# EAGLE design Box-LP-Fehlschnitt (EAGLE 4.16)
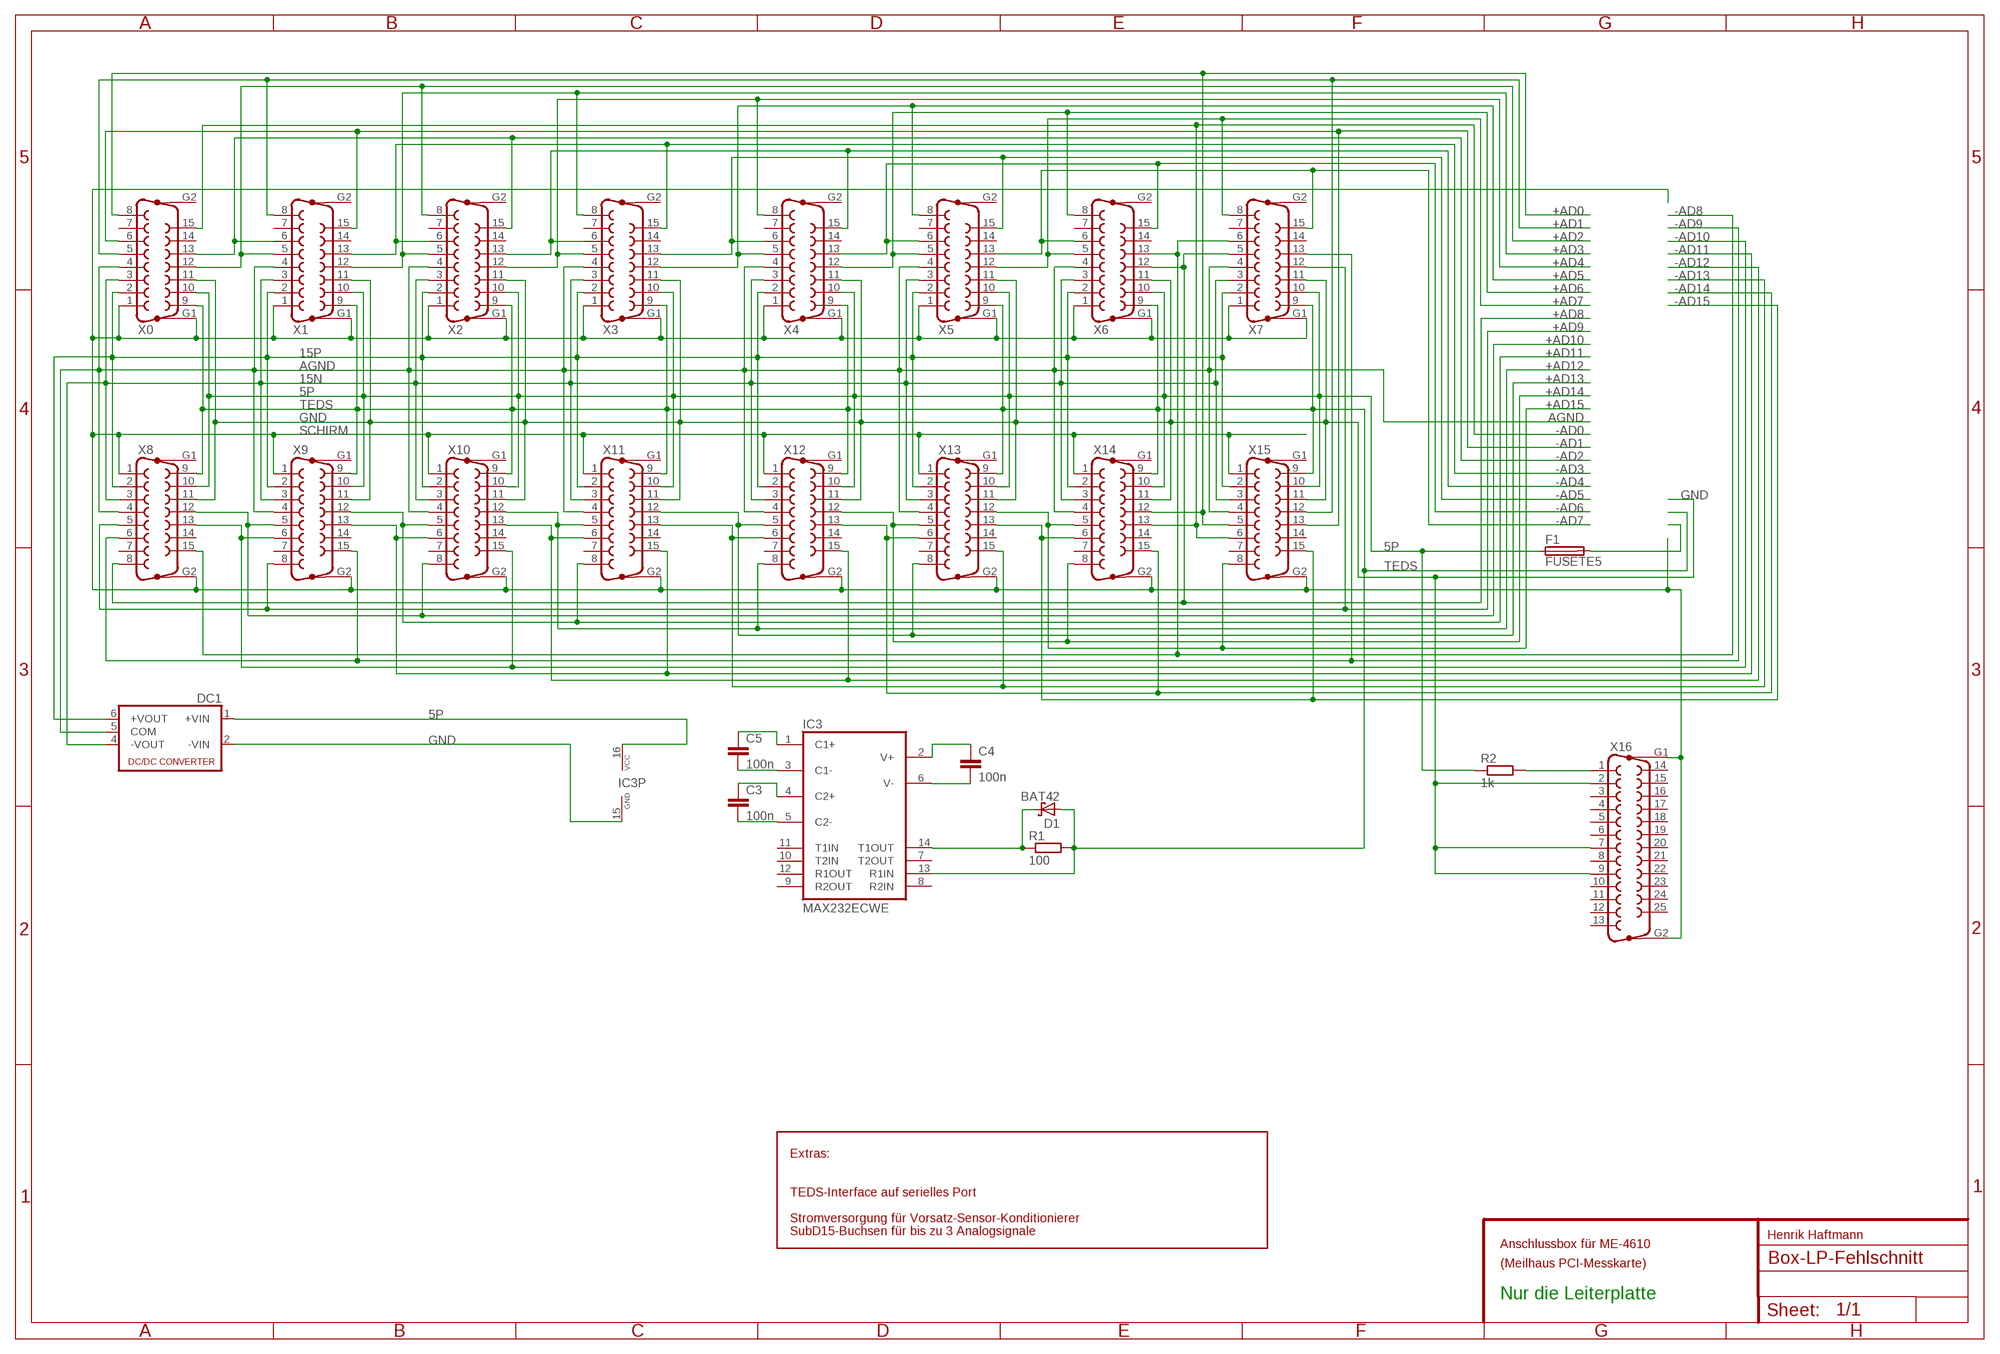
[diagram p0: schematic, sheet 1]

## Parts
C3  100n  C-EUC0603K  [C0603K]
C4  100n  C-EUC0603K  [C0603K]
C5  100n  C-EUC0603K  [C0603K]
D1  BAT42  [DO35-10]
DC1  NMA  [NMA]
F1  FUSETE5  [TE5]
IC3  MAX232ECWE  [SO16L]
R1  100  R-EU_R0805  [R0805]
R2  1k  R-EU_R0805  [R0805]
X0  F15VP  [F15VP]
X1  F15VP  [F15VP]
X2  F15VP  [F15VP]
X3  F15VP  [F15VP]
X4  F15VP  [F15VP]
X5  F15VP  [F15VP]
X6  F15VP  [F15VP]
X7  F15VP  [F15VP]
X8  F15VP  [F15VP]
X9  F15VP  [F15VP]
X10  F15VP  [F15VP]
X11  F15VP  [F15VP]
X12  F15VP  [F15VP]
X13  F15VP  [F15VP]
X14  F15VP  [F15VP]
X15  F15VP  [F15VP]
X16  F25VP  [F25VP]

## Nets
5P: DC1.1(+VIN) F1.1 IC3.16(VCC) R2.1 X0.10 X1.10 X2.10 X3.10 X4.10 X5.10 X6.10 X7.10 X8.10 X9.10 X10.10 X11.10 X12.10 X13.10 X14.10 X15.10
15N: DC1.4(-VOUT) X0.3 X1.3 X2.3 X3.3 X4.3 X5.3 X6.3 X7.3 X8.3 X9.3 X10.3 X11.3 X12.3 X13.3 X14.3 X15.3
15P: DC1.6(+VOUT) X0.2 X1.2 X2.2 X3.2 X4.2 X5.2 X6.2 X7.2 X8.2 X9.2 X10.2 X11.2 X12.2 X13.2 X14.2 X15.2
+AD0: X0.8 X14.12 X15.5
+AD1: X0.5 X1.8 X15.12
+AD2: X0.12 X1.5 X2.8
+AD3: X1.12 X2.5 X3.8
+AD4: X2.12 X3.5 X4.8
+AD5: X3.12 X4.5 X5.8
+AD6: X4.12 X5.5 X6.8
+AD7: X5.12 X6.5 X7.8
+AD8: X6.12 X7.5 X8.8
+AD9: X7.12 X8.5 X9.8
+AD10: X8.12 X9.5 X10.8
+AD11: X9.12 X10.5 X11.8
+AD12: X10.12 X11.5 X12.8
+AD13: X11.12 X12.5 X13.8
+AD14: X12.12 X13.5 X14.8
+AD15: X13.12 X14.5 X15.8
-AD0: X0.15 X14.13 X15.6
-AD1: X0.6 X1.15 X15.13
-AD2: X0.13 X1.6 X2.15
-AD3: X1.13 X2.6 X3.15
-AD4: X2.13 X3.6 X4.15
-AD5: X3.13 X4.6 X5.15
-AD6: X4.13 X5.6 X6.15
-AD7: X5.13 X6.6 X7.15
-AD8: X6.13 X7.6 X8.15
-AD9: X7.13 X8.6 X9.15
-AD10: X8.13 X9.6 X10.15
-AD11: X9.13 X10.6 X11.15
-AD12: X10.13 X11.6 X12.15
-AD13: X11.13 X12.6 X13.15
-AD14: X12.13 X13.6 X14.15
-AD15: X13.13 X14.6 X15.15
AGND: DC1.5(COM) X0.4 X1.4 X2.4 X3.4 X4.4 X5.4 X6.4 X7.4 X8.4 X9.4 X10.4 X11.4 X12.4 X13.4 X14.4 X15.4
GND: DC1.2(-VIN) IC3.15(GND) X0.11 X1.11 X2.11 X3.11 X4.11 X5.11 X6.11 X7.11 X8.11 X9.11 X10.11 X11.11 X12.11 X13.11 X14.11 X15.11 X16.2 X16.7 X16.9
N$1: R2.2 X16.1
N$2: F1.2
N$27: C3.2 IC3.5(C2-)
N$28: C5.2 IC3.3(C1-)
N$29: C5.1 IC3.1(C1+)
N$30: C3.1 IC3.4(C2+)
N$31: C4.2 IC3.6(V-)
N$32: C4.1 IC3.2(V+)
N$36: D1.C IC3.14(T1OUT) R1.1
SCHIRM: X0.1 X0.G1 X1.1 X1.G1 X2.1 X2.G1 X3.1 X3.G1 X4.1 X4.G1 X5.1 X5.G1 X6.1 X6.G1 X7.1 X7.G1 X8.1 X8.G2 X9.1 X9.G2 X10.1 X10.G2 X11.1 X11.G2 X12.1 X12.G2 X13.1 X13.G2 X14.1 X14.G2 X15.1 X15.G2 X16.G1 X16.G2
TEDS: D1.A IC3.13(R1IN) R1.2 X0.9 X1.9 X2.9 X3.9 X4.9 X5.9 X6.9 X7.9 X8.9 X9.9 X10.9 X11.9 X12.9 X13.9 X14.9 X15.9
Unconnected: IC3.7(T2OUT) IC3.8(R2IN) IC3.9(R2OUT) IC3.10(T2IN) IC3.11(T1IN) IC3.12(R1OUT) X0.7 X0.14 X0.G2 X1.7 X1.14 X1.G2 X2.7 X2.14 X2.G2 X3.7 X3.14 X3.G2 X4.7 X4.14 X4.G2 X5.7 X5.14 X5.G2 X6.7 X6.14 X6.G2 X7.7 X7.14 X7.G2 X8.7 X8.14 X8.G1 X9.7 X9.14 X9.G1 X10.7 X10.14 X10.G1 X11.7 X11.14 X11.G1 X12.7 X12.14 X12.G1 X13.7 X13.14 X13.G1 X14.7 X14.14 X14.G1 X15.7 X15.14 X15.G1 X16.3 X16.4 X16.5 X16.6 X16.8 X16.10 X16.11 X16.12 X16.13 X16.14 X16.15 X16.16 X16.17 X16.18 X16.19 X16.20 X16.21 X16.22 X16.23 X16.24 X16.25

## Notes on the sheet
- Extras:
- TEDS-Interface auf serielles Port
- Stromversorgung für Vorsatz-Sensor-Konditionierer
- SubD15-Buchsen für bis zu 3 Analogsignale
- Henrik Haftmann
- Anschlussbox für ME-4610
- (Meilhaus PCI-Messkarte)
- Nur die Leiterplatte

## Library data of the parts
C3-C5 = rcl:C-EU: CAPACITOR, European symbol
D1 = diode:BAT42: DIODE
DC1 = dc-dc-converter:NMA: DC-DC CONVERTER
F1 = fuse:FUSE: Fuse
IC3 = maxim:MAX232ECWE: RS232 TRANSEIVER
R1 R2 = rcl:R-EU_: RESISTOR, European symbol
X0 X1-X15 = con-subd:F15VP: SUB-D
X16 = con-subd:F25VP: SUB-D

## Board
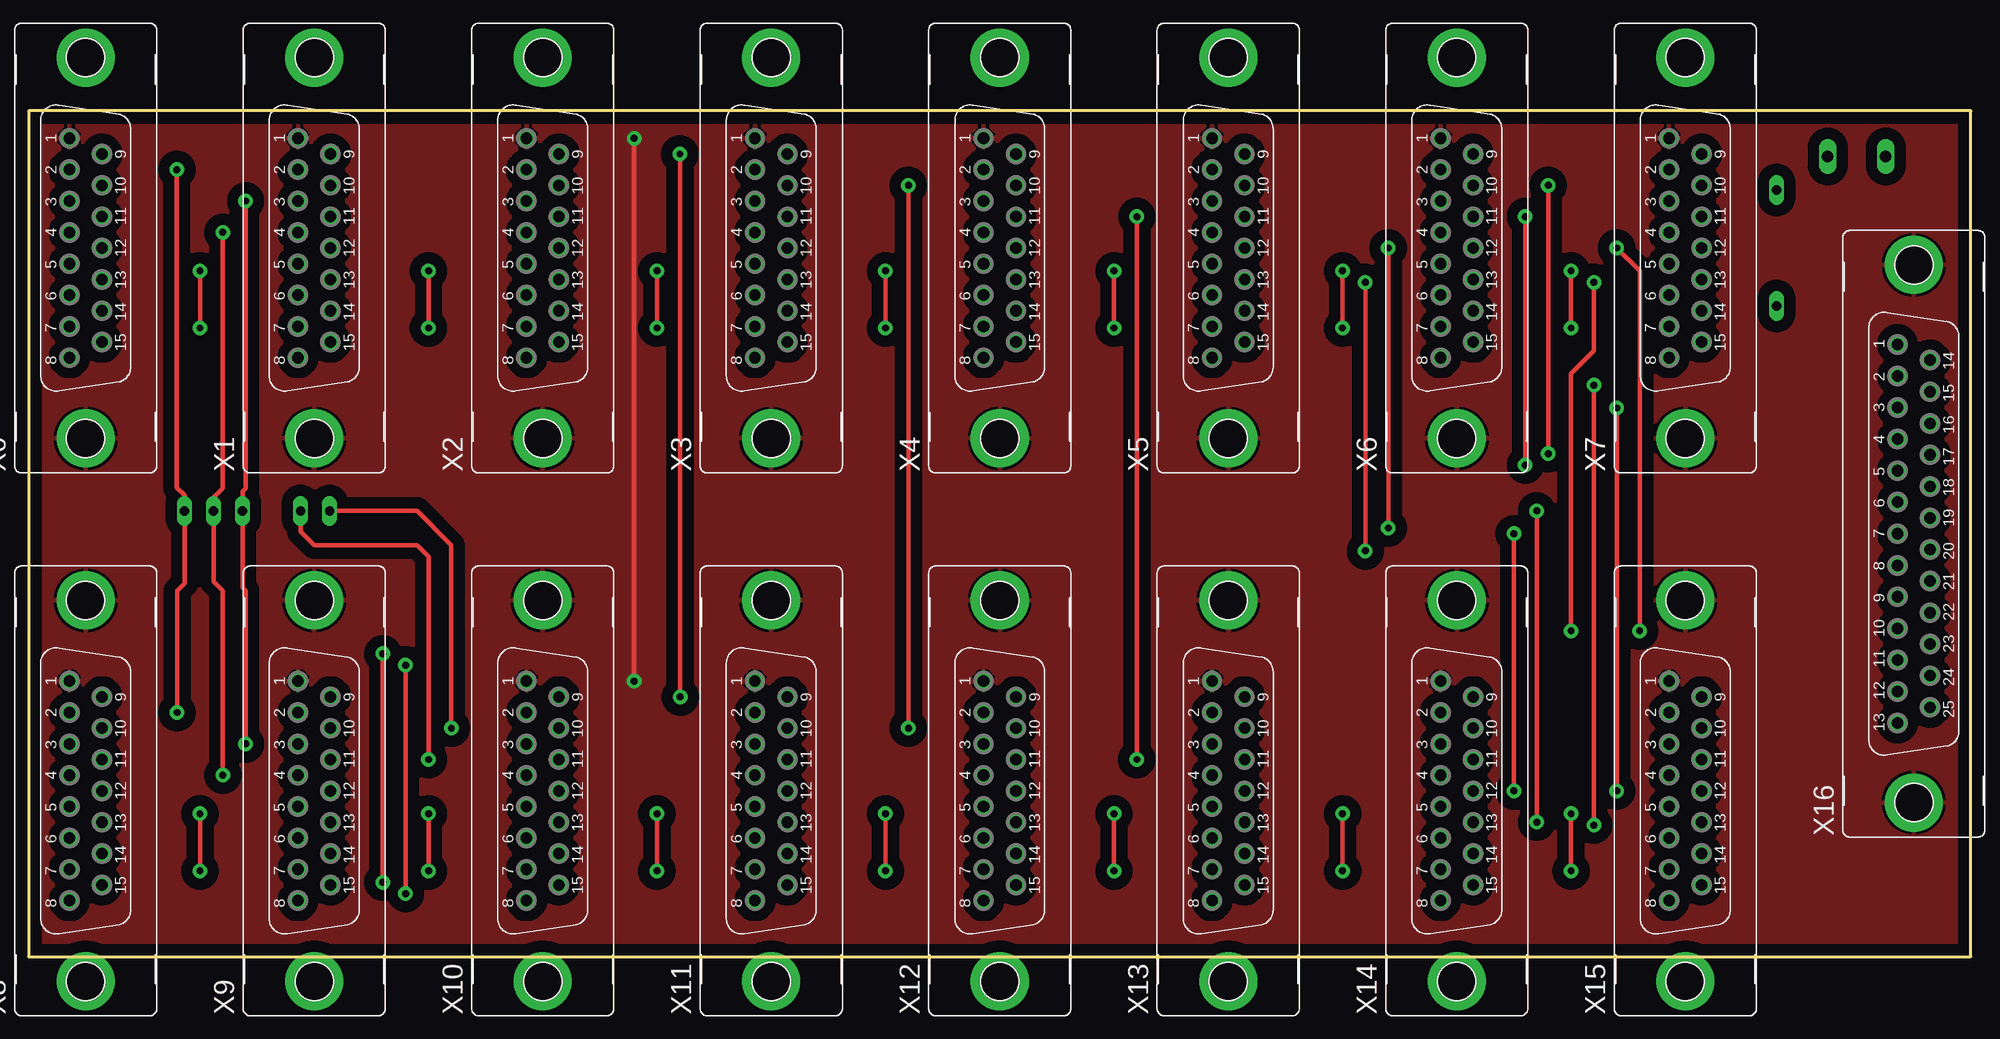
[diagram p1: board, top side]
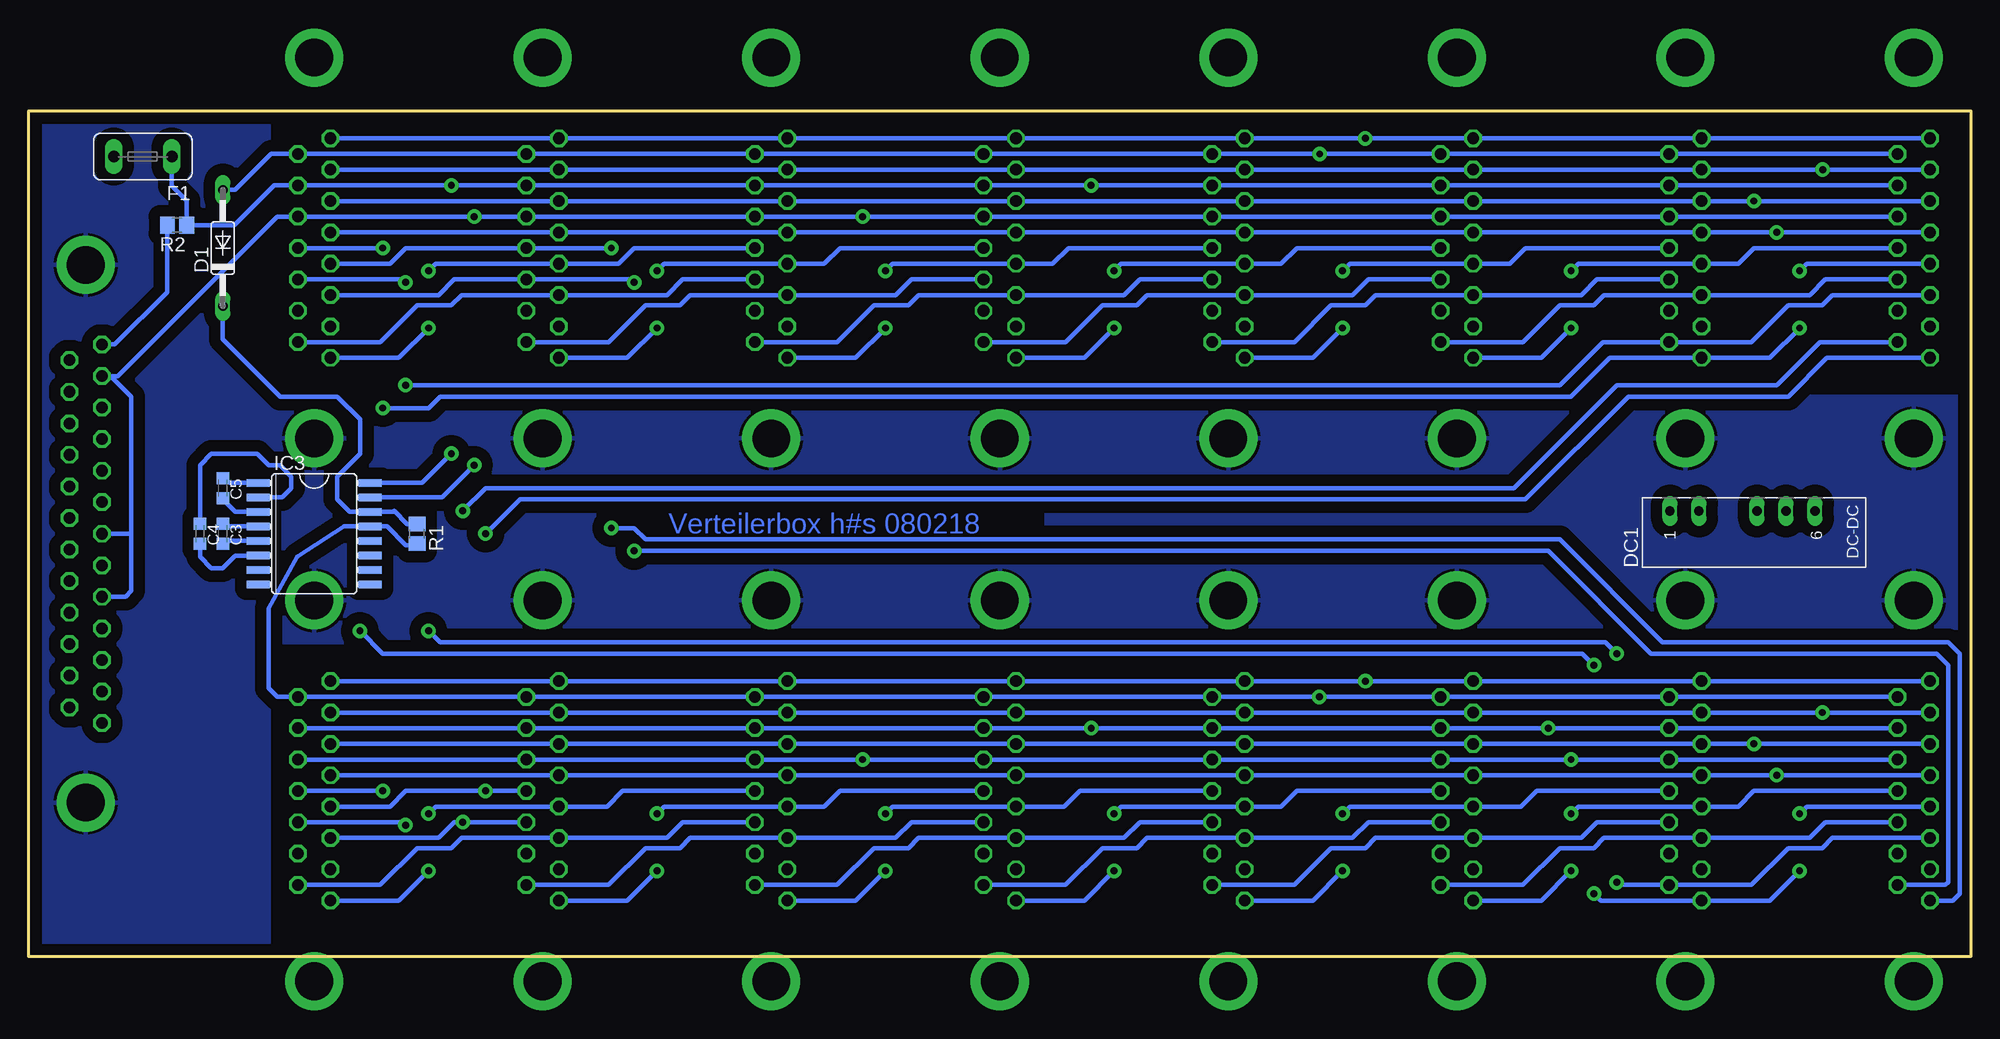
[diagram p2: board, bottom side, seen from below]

Size 170 x 74 mm. Coordinates in mm from the lower left corner, seen from the top.
Outline: 0,0 170,0 170,74 0,74 0,0
Copper layers (1*16): Top 0.035mm / dielectric 1.5mm / Bottom 0.035mm
Design rules "Felber": minimum track width 0.15mm, minimum drill 0.3mm, track to track 0.15mm, track to pad 0.15mm, pad to pad 0.15mm, via to via 0.15mm, smd to smd 0mil, copper to edge 0.3mm, drill to drill 0.3mm, minimum pad ring 10mil, minimum via ring 8mil, stop-mask expansion 4mil, vias tented up to drill 0mil, thermal gap 10mil

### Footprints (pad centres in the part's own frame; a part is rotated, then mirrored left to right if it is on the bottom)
C0603K = smd 1.05 x 1.08: 1 -0.875,0; 2 0.875,0
DO35-10 = drill 0.813 long: A 5.08,0; C -5.08,0
NMA = drill 0.813 long: 1 0,6.35; 2 0,3.81; 4 0,-1.27; 5 0,-3.81; 6 0,-6.35
TE5 = drill 1.016 long: 1 -2.54,0; 2 2.54,0
SO16L = smd 0.66 x 2.032: 1 -4.445,-4.902; 2 -3.175,-4.902; 3 -1.905,-4.902; 4 -0.635,-4.902; 5 0.635,-4.902; 6 1.905,-4.902; 7 3.175,-4.902; 8 4.445,-4.902; 9 4.445,4.902; 10 3.175,4.902; 11 1.905,4.902; 12 0.635,4.902; 13 -0.635,4.902; 14 -1.905,4.902; 15 -3.175,4.902; 16 -4.445,4.902
R0805 = smd 1.3 x 1.5: 1 -0.85,0; 2 0.85,0
F15VP = drill 1.016 octagon: 1 9.601,1.422; 2 6.858,1.422; 3 4.115,1.422; 4 1.372,1.422; 5 -1.372,1.422; 6 -4.115,1.422; 7 -6.858,1.422; 8 -9.601,1.422; 9 8.23,-1.422; 10 5.486,-1.422; 11 2.743,-1.422; 12 0,-1.422; 13 -2.743,-1.422; 14 -5.486,-1.422; 15 -8.23,-1.422 | drill 3.302 pad 5.08 round: G1 -16.662,0; G2 16.662,0
F25VP = drill 1.016 octagon: 1 16.561,1.422; 2 13.792,1.422; 3 11.049,1.422; 4 8.28,1.422; 5 5.512,1.422; 6 2.769,1.422; 7 0,1.422; 8 -2.769,1.422; 9 -5.512,1.422; 10 -8.28,1.422; 11 -11.049,1.422; 12 -13.792,1.422; 13 -16.561,1.422; 14 15.189,-1.422; 15 12.421,-1.422; 16 9.652,-1.422; 17 6.909,-1.422; 18 4.14,-1.422; 19 1.372,-1.422; 20 -1.372,-1.422; 21 -4.14,-1.422; 22 -6.909,-1.422; 23 -9.652,-1.422; 24 -12.421,-1.422; 25 -15.189,-1.422 | drill 3.302 pad 5.08 round: G1 -23.52,0; G2 23.52,0

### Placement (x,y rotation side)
C3  153,37 270 bottom
C4  155,37 270 bottom
C5  153,41 270 bottom
D1  153,62 90 bottom
DC1  20,39 90 bottom
F1  160,70 180 bottom
IC3  145,37 270 bottom
R1  136,37 270 bottom
R2  157,64 180 bottom
X0  5,62 90 top
X1  25,62 90 top
X2  45,62 90 top
X3  65,62 90 top
X4  85,62 90 top
X5  105,62 90 top
X6  125,62 90 top
X7  145,62 90 top
X8  5,14.5 90 top
X9  25,14.5 90 top
X10  45,14.5 90 top
X11  65,14.5 90 top
X12  85,14.5 90 top
X13  105,14.5 90 top
X14  125,14.5 90 top
X15  145,14.5 90 top
X16  165,37 90 top

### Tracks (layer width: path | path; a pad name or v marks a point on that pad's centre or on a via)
5P  (via drill 0.6 pad 1.27)
  Top 0.406: 77,37 v77,67.49 | 77,37 | v77,19.99 77,37 | DC1.1 34,39 37,36 v37,19.99 | v133,67.49 v133,44
  Bottom 0.406: X0.10 X1.10 X2.10 X3.10 v77,67.49 X4.10 X5.10 X6.10 v133,67.49 X7.10 148.51,67.49 152,64 R2.1 156.15,66.15 157.46,67.46 F1.1 | X8.10 X9.10 v37,19.99 X10.10 X11.10 v77,19.99 X12.10 X13.10 X14.10 X15.10 | IC3.16 135.56,41.45 v133,44
15N  (via drill 0.6 pad 1.27)
  Top 0.406: v19,66.11 19,41 18.73,40.73 DC1.4 18.73,32.27 19,32 v19,18.61
  Bottom 0.406: X0.3 v19,66.11 X1.3 X2.3 X3.3 X4.3 X5.3 X6.3 X7.3 | X8.3 v19,18.61 X9.3 X10.3 X11.3 X12.3 X13.3 X14.3 X15.3
15P  (via drill 0.6 pad 1.27)
  Top 0.406: v13,21.36 13,32 13.65,32.65 DC1.6 13.65,40.35 12.98,41.02 v12.98,68.86
  Bottom 0.406: X0.2 v12.98,68.86 X1.2 X2.2 X3.2 X4.2 X5.2 X6.2 X7.2 | X8.2 v13,21.36 X9.2 X10.2 X11.2 X12.2 X13.2 X14.2 X15.2
+AD0  (via drill 0.6 pad 1.27)
  Top 0.406: v130,37 v130,14.5
  Bottom 0.406: X14.12 v130,14.5 137,14.5 138.37,13.13 X15.5 | X0.8 12.6,52.4 16,49 30,49 39,40 127,40 v130,37
+AD1  (via drill 0.6 pad 1.27)
  Top 0.406: v15,60 v15,55 | v139,48 v139,14.5
  Bottom 0.406: X0.5 14.37,60.63 v15,60 | v15,55 17.6,52.4 X1.8 31.6,52.4 35,49 134,49 135,48 v139,48 | v139,14.5 X15.12
+AD2  (via drill 0.6 pad 1.27)
  Top 0.406: v35,60 v35,55
  Bottom 0.406: X0.12 19,62 20.37,60.63 X1.5 34.37,60.63 v35,60 | X2.8 37.6,52.4 v35,55
+AD3  (via drill 0.6 pad 1.27)
  Top 0.406: v55,60 v55,55
  Bottom 0.406: X1.12 39,62 40.37,60.63 X2.5 54.37,60.63 v55,60 | X3.8 57.6,52.4 v55,55
+AD4  (via drill 0.6 pad 1.27)
  Top 0.406: v75,60 v75,55
  Bottom 0.406: X2.12 59,62 60.37,60.63 X3.5 74.37,60.63 v75,60 | X4.8 77.6,52.4 v75,55
+AD5  (via drill 0.6 pad 1.27)
  Top 0.406: v95,60 v95,55
  Bottom 0.406: X3.12 79,62 80.37,60.63 X4.5 94.37,60.63 v95,60 | X5.8 97.6,52.4 v95,55
+AD6  (via drill 0.6 pad 1.27)
  Top 0.406: v115,60 v115,55
  Bottom 0.406: X4.12 99,62 100.37,60.63 X5.5 114.37,60.63 v115,60 | X6.8 117.6,52.4 v115,55
+AD7  (via drill 0.6 pad 1.27)
  Top 0.406: v135,60 v135,55
  Bottom 0.406: X5.12 117,62 118.37,60.63 X6.5 134.37,60.63 v135,60 | X7.8 137.6,52.4 v135,55
+AD8  (via drill 0.6 pad 1.27)
  Top 0.406: v119,37.5 v119,62
  Bottom 0.406: X7.5 138.37,60.63 137,62 X6.12 v119,62 | X8.8 1.6,4.9 1,5.5 1,26.5 2,27.5 27,27.5 36,36.5 116,36.5 117,37.5 v119,37.5
+AD9  (via drill 0.6 pad 1.27)
  Top 0.406: v15,12.5 v15,7.5 | v33,5.5 v33,25.5 | v141,28.5 141,60 v139,62
  Bottom 0.406: X8.5 14.37,13.13 v15,12.5 | v15,7.5 17.6,4.9 X9.8 32.4,4.9 v33,5.5 | v33,25.5 34,26.5 139,26.5 v141,28.5 | v139,62 X7.12
+AD10  (via drill 0.6 pad 1.27)
  Top 0.406: v35,12.5 v35,7.5
  Bottom 0.406: v35,12.5 34.37,13.13 X9.5 20.37,13.13 19,14.5 X8.12 | X10.8 37.6,4.9 v35,7.5
+AD11  (via drill 0.6 pad 1.27)
  Top 0.406: v55,12.5 v55,7.5
  Bottom 0.406: v55,12.5 54.37,13.13 X10.5 39.37,13.13 38,14.5 X9.12 | X11.8 57.6,4.9 v55,7.5
+AD12  (via drill 0.6 pad 1.27)
  Top 0.406: v75,12.5 v75,7.5
  Bottom 0.406: v75,12.5 74.37,13.13 X11.5 60.37,13.13 59,14.5 X10.12 | X12.8 77.6,4.9 v75,7.5
+AD13  (via drill 0.6 pad 1.27)
  Top 0.406: v95,12.5 v95,7.5
  Bottom 0.406: v95,12.5 94.37,13.13 X12.5 79.37,13.13 78,14.5 X11.12 | X13.8 97.6,4.9 v95,7.5
+AD14  (via drill 0.6 pad 1.27)
  Top 0.406: v115,12.5 v115,7.5
  Bottom 0.406: v115,12.5 114.37,13.13 X13.5 100.37,13.13 99,14.5 X12.12 | X14.8 117.6,4.9 v115,7.5
+AD15  (via drill 0.6 pad 1.27)
  Top 0.406: v135,12.5 v135,7.5
  Bottom 0.406: v135,12.5 134.37,13.13 X14.5 119.37,13.13 118,14.5 X13.12 | X15.8 137.6,4.9 v135,7.5
-AD0  (via drill 0.6 pad 1.27)
  Top 0.406: v132,39 v132,11.76
  Bottom 0.406: X14.13 v132,11.76 132.74,11.76 134.12,10.39 X15.6 | X0.15 13.23,53.77 17,50 31,50 40,41 130,41 v132,39
-AD1  (via drill 0.6 pad 1.27)
  Top 0.406: v137,50 v137,11.5
  Bottom 0.406: X0.6 12.12,57.89 13,57 16,57 19.23,53.77 X1.15 32.23,53.77 36,50 v137,50 | X15.13 137.26,11.76 v137,11.5
-AD2
  Bottom 0.406: X0.13 12.74,59.26 14.12,57.89 X1.6 32.12,57.89 33,57 36,57 39.23,53.77 X2.15
-AD3
  Bottom 0.406: X1.13 32.74,59.26 34.12,57.89 X2.6 52.12,57.89 53,57 56,57 59.23,53.77 X3.15
-AD4
  Bottom 0.406: X2.13 52.74,59.26 54.12,57.89 X3.6 72.11,57.89 73,57 76,57 79.23,53.77 X4.15
-AD5
  Bottom 0.406: X3.13 72.74,59.26 74.11,57.89 X4.6 92.11,57.89 93,57 96,57 99.23,53.77 X5.15
-AD6
  Bottom 0.406: X6.15 119.23,53.77 116,57 113,57 112.11,57.89 X5.6 94.11,57.89 92.74,59.26 X4.13
-AD7
  Bottom 0.406: X5.13 112.74,59.26 114.11,57.89 X6.6 132.12,57.89 133,57 136,57 139.23,53.77 X7.15
-AD8  (via drill 0.6 pad 1.27)
  Top 0.406: v117,35.5 v117,59
  Bottom 0.406: X7.6 134.12,57.89 132.74,59.26 X6.13 117.26,59.26 v117,59 | X8.15 2.23,6.27 2,6.5 2,25.5 3,26.5 28,26.5 37,35.5 v117,35.5
-AD9  (via drill 0.6 pad 1.27)
  Top 0.406: v31,6.5 v31,26.5 | v135,28.5 135,51 137,53 v137,59
  Bottom 0.406: X8.6 12.12,10.39 13,9.5 16,9.5 19.23,6.27 X9.15 30.77,6.27 v31,6.5 | v31,26.5 32,27.5 134,27.5 v135,28.5 | X7.13 137.26,59.26 v137,59
-AD10
  Bottom 0.406: X10.15 39.23,6.27 36,9.5 33,9.5 32.12,10.39 X9.6 14.12,10.39 12.74,11.76 X8.13
-AD11
  Bottom 0.406: X11.15 59.23,6.27 56,9.5 53,9.5 52.12,10.39 X10.6 34.12,10.39 32.74,11.76 X9.13
-AD12
  Bottom 0.406: X12.15 79.23,6.27 76,9.5 73,9.5 72.11,10.39 X11.6 54.12,10.39 52.74,11.76 X10.13
-AD13
  Bottom 0.406: X13.15 99.23,6.27 96,9.5 93,9.5 92.11,10.39 X12.6 74.11,10.39 72.74,11.76 X11.13
-AD14
  Bottom 0.406: X14.15 119.23,6.27 116,9.5 113,9.5 112.11,10.39 X13.6 94.11,10.39 92.74,11.76 X12.13
-AD15
  Bottom 0.406: X15.15 139.23,6.27 136,9.5 133,9.5 132.12,10.39 X14.6 114.11,10.39 112.74,11.76 X13.13
AGND  (via drill 0.6 pad 1.27)
  Top 0.406: v17,63.37 17,41 16.19,40.19 DC1.5 16.19,32.81 17,32 v17,15.87
  Bottom 0.406: X0.4 v17,63.37 X1.4 X2.4 X3.4 X4.4 X5.4 X6.4 X7.4 | X8.4 v17,15.87 X9.4 X10.4 X11.4 X12.4 X13.4 X14.4 X15.4
GND  (via drill 0.6 pad 1.27)
  Top 0.406: v97.01,64.74 97.01,37.01 97,37 v97,17.24 | DC1.2 23.81,37.19 25,36 34,36 35,35 v35,17.24 | v131,64.74 v131,43
  Bottom 0.406: X0.11 X1.11 X2.11 X3.11 X4.11 v97.01,64.74 X5.11 X6.11 v131,64.74 X7.11 148.26,64.74 162.21,50.79 X16.2 162.79,50.79 161,49 161,37 | X8.11 X9.11 v35,17.24 X10.11 X11.11 X12.11 v97,17.24 X13.11 X14.11 X15.11 | X16.9 161.51,31.49 161,32 161,37 | 161,37 X16.7 | IC3.15 133.82,40.17 v131,43
N$1
  Bottom 0.406: X16.1 162.44,53.56 157.85,58.15 R2.2
N$27
  Bottom 0.406: C3.2 153,36 152.63,36.37 IC3.5
N$28
  Bottom 0.406: C5.2 153,40 151.91,38.91 IC3.3
N$29
  Bottom 0.406: C5.1 153,42 152.44,41.45 IC3.1
N$30
  Bottom 0.406: C3.1 153,38 152.63,37.63 IC3.4
N$31
  Bottom 0.406: IC3.6 151.91,35.09 153,34 154,34 155,35 C4.2
N$32
  Bottom 0.406: IC3.2 147.82,40.17 147,41 147,42 148,43 149,43 150,44 154,44 155,43 C4.1
N$36
  Bottom 0.406: D1.C 153,54 148,49 143,49 141,47 141,44 143,42 143,40 141.91,38.91 IC3.14 138.09,38.91 138,39 136.85,37.85 R1.1
SCHIRM  (via drill 0.6 pad 1.27)
  Top 0.406: v53,24.1 53,54 v53,71.6
  Bottom 0.406: X0.1 X1.1 X2.1 v53,71.6 X3.1 X4.1 X5.1 X6.1 X7.1 | X8.1 X9.1 X10.1 v53,24.1 X11.1 X12.1 X13.1 X14.1 X15.1
  pour Top (isolate 1): 1,73 169,73 169,1 1,1
  pour Bottom (isolate 1): 1,49 149,49 149,73 169,73 169,1 149,1 149,27.5 1,26.5
TEDS  (via drill 0.6 pad 1.27)
  Top 0.406: v57.03,22.73 57.03,37.97 57,38 v57,70.23
  Bottom 0.406: X0.9 X1.9 X2.9 v57,70.23 X3.9 X4.9 X5.9 X6.9 X7.9 148.77,70.23 151.92,67.08 D1.A | X8.9 X9.9 X10.9 v57.03,22.73 X11.9 X12.9 X13.9 X14.9 X15.9 148.23,22.73 149,23.5 149,30.5 146.5,35 142.37,37.63 IC3.13 138.63,37.63 137,36 136,36 R1.2

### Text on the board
Bottom: Verteilerbox h#s 080218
